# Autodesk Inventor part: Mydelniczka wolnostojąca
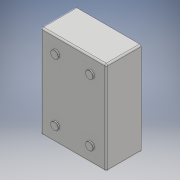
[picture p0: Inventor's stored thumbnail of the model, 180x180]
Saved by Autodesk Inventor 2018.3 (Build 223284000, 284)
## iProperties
Created: 2020-12
Part Number: Mydelniczka wolnostojąca
Material: Ogólny
Document SubType Name: Modeling
Designer: Verical
Density: 1 g/cm^3
Appearance: Domyślna
Author: Verical
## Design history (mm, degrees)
derived "Mydelniczka wolnostojąca.iam"
node "Bryła1"
node "Mydelniczka pojemnik prototyp.ipt:1"
node "Kratka.ipt:1"
node "nóżka.ipt:1"
node "nóżka.ipt:2"
node "nóżka.ipt:3"
node "nóżka.ipt:4"
